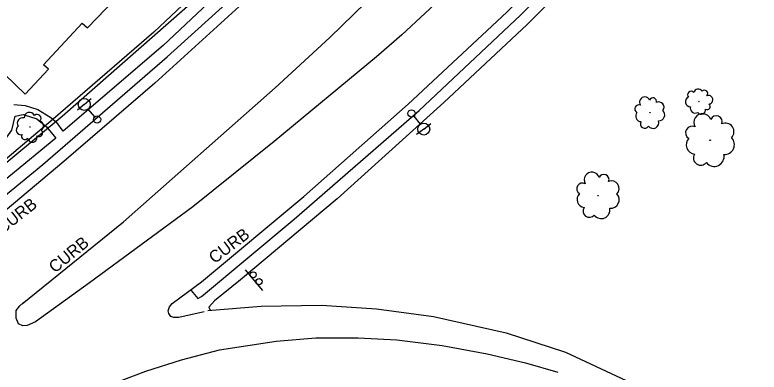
# Model space of a CAD drawing. Extents: x 1722896 to 1754269, y 648279 to 666297.
# Drawn here: x 1725529 to 1725838.8, y 657047.8 to 657196.4 of the extents above; entities that cross this region are included whole.
import ezdxf

# ---------------------------------------------------------------- set-up
doc = ezdxf.new("R2010")
doc.units = 0
for name, color, linetype in [('DESIGN - CENTERLINE - Proposed Text', 7, 'Continuous'), ('DESIGN - PUBLIC HEARING - Shapes', 7, 'Continuous'), ('DESIGN - SCRATCH - User 1', 7, 'Continuous'), ('SURVEY - CENTERLINE - Preliminary Text', 7, 'Continuous'), ('SURVEY - DTM - Breaklines', 7, 'Continuous'), ('SURVEY - VEGETATION - Features with Text', 7, 'Continuous')]:
    doc.layers.add(name, color=color, linetype=linetype)

msp = doc.modelspace()

# ---------------------------------------------------------------- linework, layer by layer
at = {"layer": 'DESIGN - CENTERLINE - Proposed Text'}
for points in [[(1725516.27, 657179.89), (1725533.34, 657163.48), (1725543.06, 657173.81), (1725540.98, 657175.6), (1725557.07, 657192.96), (1725559.27, 657191.08), (1725578.04, 657210.77)], [(1725528.54, 657159.22), (1725533.32, 657158.72), (1725538.57, 657157.14), (1725544.02, 657153.76), (1725546.52, 657151.61)], [(1725488.44, 657145.73), (1725496.96, 657140.59), (1725503.76, 657137.68), (1725510.37, 657137.1), (1725517.44, 657139.1), (1725524.03, 657143.28), (1725527.77, 657148.51), (1725529.17, 657154.37), (1725532.5, 657155.05), (1725538.16, 657153.17), (1725542.18, 657149.86)]]:
    msp.add_lwpolyline(points, dxfattribs=at)
at = {"layer": 'DESIGN - PUBLIC HEARING - Shapes'}
msp.add_line((1725632.15, 657081.75), (1725624.93, 657090.32), dxfattribs=at)
for centre in [(1725628.21, 657088.33), (1725630.62, 657085.46)]:
    msp.add_circle(centre, 1.25, dxfattribs=at)
at = {"layer": 'DESIGN - SCRATCH - User 1'}
msp.add_lwpolyline([(1725742.05, 657346.53), (1725723, 657325.09), (1725698.94, 657299.79), (1725619.93, 657220.56), (1725586.88, 657189.31), (1725544.91, 657153.09), (1725506.52, 657120.56), (1725470.29, 657167.27), (1725457.27, 657184.7), (1725456.5, 657184.15), (1725477.5, 657156.42), (1725506.66, 657119.48), (1725548.74, 657154.33), (1725605.42, 657204.22), (1725621.69, 657220.53), (1725699.14, 657298.47), (1725725.52, 657326.03), (1725742.5, 657345.81), (1725742.05, 657346.53)], dxfattribs=at)
at = {"layer": 'SURVEY - CENTERLINE - Preliminary Text'}
for points in [[(1725833.12, 657482.75), (1725835.66, 657466.48), (1725834.6, 657454.24), (1725831.44, 657439.43), (1725826.41, 657426.41), (1725818.4, 657413.79), (1725808.1, 657399.25), (1725796.47, 657385.67), (1725752.65, 657333.53), (1725710.25, 657287.4), (1725667.95, 657244.36), (1725628.49, 657205.64), (1725587.23, 657167.97), (1725549.38, 657135.48)], [(1725532.07, 657076.3), (1725574.2, 657110.35), (1725637.37, 657166.1), (1725660.07, 657187.1), (1725690.07, 657216.25), (1725721.81, 657248.12), (1725754.91, 657284.07), (1725786.69, 657319.12), (1725817.79, 657356.98), (1725845.97, 657390.57), (1725873.52, 657421.22), (1725898.55, 657448.81), (1725901.06, 657449.44), (1725903.37, 657448.44), (1725903.44, 657445.72), (1725899.57, 657420.45), (1725897.4, 657414.19), (1725893.15, 657407.78)], [(1725893.15, 657407.78), (1725869.14, 657378.83), (1725829.83, 657332.28), (1725792.43, 657289.73), (1725756.4, 657252.29), (1725723.24, 657219.05), (1725690, 657188.11), (1725679.58, 657178.98)], [(1725607.83, 657072.92), (1725597.21, 657070.49), (1725595.18, 657070.52), (1725593.88, 657071), (1725593.1, 657072.24), (1725592.86, 657073.31), (1725593.3, 657074.94), (1725594.49, 657076.33), (1725606.69, 657085.38), (1725649.32, 657120.94), (1725692.63, 657159.31), (1725733.76, 657197.57), (1725789.89, 657253.54), (1725817.33, 657283.16), (1725853.8, 657323.83), (1725890.03, 657366.92), (1725899.06, 657378.21), (1725901.84, 657379.26), (1725903.98, 657378.15), (1725905.38, 657375.6), (1725908.82, 657364.43)], [(1725602.37, 657081.85), (1725605.17, 657078.45), (1725606.68, 657079.3), (1725645.31, 657111.4), (1725697.24, 657156.73), (1725739.42, 657196.37), (1725786.94, 657243.71), (1725825.47, 657284.65), (1725865.64, 657330.37), (1725893.13, 657362.83), (1725889.47, 657365.97)], [(1725908.58, 657363.1), (1725896.71, 657359.6), (1725868.74, 657326.19), (1725830.57, 657282.8), (1725786.13, 657236.24), (1725742.28, 657192.44), (1725707.55, 657159.95), (1725663.1, 657119.88), (1725622.86, 657086.23), (1725612.13, 657077.45), (1725609.79, 657074.87), (1725610.29, 657073.63)], [(1725515.89, 657107.45), (1725512.65, 657111.3), (1725540.69, 657134.27), (1725592.43, 657179.06), (1725625.37, 657208.98), (1725663.1, 657245.93), (1725711.56, 657295.92), (1725740.56, 657328.09), (1725752.86, 657342.45)], [(1725748.06, 657344.39), (1725726.31, 657319.44), (1725682.49, 657272.69), (1725637.54, 657227.74), (1725590.72, 657183.75), (1725549.07, 657148.05), (1725546.52, 657151.61)], [(1725679.58, 657178.98), (1725636.97, 657143.75), (1725603.07, 657116.66), (1725560.02, 657084.91), (1725537.54, 657068.69), (1725534.19, 657067.27), (1725532.28, 657067.12), (1725530.55, 657067.93), (1725529.48, 657070.25), (1725529.49, 657073.42), (1725531.14, 657075.38), (1725532.6, 657076.75)], [(1725542.18, 657149.86), (1725546.12, 657145.1), (1725506.82, 657112.97), (1725488.47, 657098.71), (1725473.8, 657087.5)], [(1725549.38, 657135.48), (1725513.49, 657105.3), (1725471.68, 657072.67), (1725427.12, 657040.14), (1725377.39, 657005.82), (1725326.06, 656972.7), (1725271.47, 656940.69), (1725219.07, 656912.28), (1725204.85, 656904.26)], [(1725609.3, 657073.42), (1725631.57, 657075.3), (1725656.58, 657075.63), (1725679.57, 657074.22), (1725703.18, 657070.99), (1725733.42, 657064.15), (1725758.22, 657056.19), (1725783.48, 657044.33), (1725805.66, 657031.11), (1725828.48, 657016.26), (1725851.08, 657001.89), (1725871.32, 656991.6), (1725892.4, 656982.66), (1725912, 656975.51), (1725934.91, 656969.34), (1725955.88, 656964.74), (1725978.63, 656963.01), (1726002.9, 656962.05), (1726019.03, 656962.18), (1726040.59, 656963.08), (1726059.81, 656966.36), (1726081.67, 656971.31), (1726099.76, 656977.82), (1726113.44, 656983.76)], [(1725568.53, 657042.56), (1725583.57, 657048.2), (1725598.33, 657052.89), (1725614.15, 657057.11), (1725637.69, 657060.76), (1725654.23, 657062.08), (1725671.9, 657062.13), (1725688.02, 657061.3), (1725706.78, 657058.89), (1725725.64, 657055.5), (1725741.5, 657051.63), (1725755.05, 657047.83)]]:
    msp.add_lwpolyline(points, dxfattribs=at)
at = {"layer": 'SURVEY - DTM - Breaklines'}
for p, q in [((1725557.9, 657159.19), (1725555.04, 657156.77)), ((1725557.9, 657159.19), (1725560.77, 657161.61)), ((1725562.26, 657154.03), (1725559.52, 657157.28)), ((1725695.01, 657154.28), (1725697.62, 657150.93)), ((1725699.16, 657148.96), (1725702.11, 657151.26)), ((1725699.16, 657148.96), (1725696.2, 657146.65))]:
    msp.add_line(p, q, dxfattribs=at)
for centre, radius in [((1725557.9, 657159.19), 2.5), ((1725694.08, 657155.46), 1.5), ((1725563.23, 657152.89), 1.5), ((1725699.16, 657148.96), 2.5)]:
    msp.add_circle(centre, radius, dxfattribs=at)
at = {"layer": 'SURVEY - VEGETATION - Features with Text'}
for centre, radius in [((1725813.68, 657160.39), 0.0634), ((1725793.31, 657155.72), 0.0761), ((1725535.32, 657149.8), 0.0694), ((1725818.4, 657144.29), 0.126), ((1725771.74, 657121.24), 0.11)]:
    msp.add_circle(centre, radius, dxfattribs=at)
for centre, radius, start, end in [((1725813.41, 657163.58), 1.95, 34.4289, 161.2745), ((1725816.02, 657163.74), 1.38, 319.1418, 136.461), ((1725791.14, 657160.11), 2.18, 22.3944, 215.8141), ((1725810.16, 657160.3), 2.06, 114.3349, 270.1734), ((1725810.48, 657163.14), 1.52, 44.5878, 219.5881), ((1725817.68, 657161.13), 1.81, 276.5232, 109.9428), ((1725788.67, 657157.33), 1.66, 65.0131, 242.3323), ((1725794.57, 657160.45), 1.5, 342.3738, 161.1194), ((1725796.99, 657158.06), 2.18, 320.2576, 117.0465), ((1725817.18, 657158.3), 1.25, 236.5025, 55.2481), ((1725535.11, 657153.65), 2.25, 26.0152, 181.8536), ((1725789.71, 657154.37), 2.35, 140.3002, 267.1458), ((1725796.97, 657154.85), 2.49, 269.3104, 46.8346), ((1725812.15, 657157.66), 2.07, 163.4391, 300.9633), ((1725814.71, 657156.91), 1.82, 214.3863, 11.1752), ((1725532.28, 657151.39), 2.26, 75.1193, 212.6436), ((1725538.23, 657153.39), 1.66, 316.2681, 131.2683), ((1725815.23, 657151.75), 3.6, 19.1055, 212.5252), ((1725820.92, 657151.99), 2.48, 339.0848, 157.8304), ((1725531.55, 657148.56), 1.99, 126.0666, 282.8555), ((1725538.8, 657150.2), 2.14, 306.1091, 72.9548), ((1725791.18, 657151.12), 1.82, 150.4591, 325.4594), ((1725794.56, 657151.69), 2.47, 220.2062, 16.0447), ((1725810.89, 657147.4), 2.74, 61.7242, 239.0433), ((1725824.69, 657147.81), 3.61, 316.9687, 113.7576), ((1725533.15, 657145.9), 1.36, 148.1827, 326.9284), ((1725539.06, 657147.34), 1.51, 230.8221, 48.1412), ((1725536.26, 657145.44), 1.98, 188.2034, 21.6231), ((1725812.32, 657142.4), 3.88, 137.0112, 263.8569), ((1725824.36, 657142.52), 4.11, 266.0214, 43.5456), ((1725814.44, 657136.9), 3.01, 147.1701, 322.1704), ((1725820.08, 657137.51), 4.09, 216.9172, 12.7557), ((1725769.12, 657127.84), 3.16, 17.7354, 211.1551), ((1725774.12, 657127.94), 2.17, 337.7147, 156.4604), ((1725765.23, 657124.12), 2.4, 60.3541, 237.6732), ((1725777.33, 657124.19), 3.16, 315.5986, 112.3875), ((1725766.38, 657119.71), 3.4, 135.6411, 262.4868), ((1725776.93, 657119.56), 3.6, 264.6513, 42.1755), ((1725768.12, 657114.85), 2.64, 145.8, 320.8003), ((1725773.08, 657115.27), 3.58, 215.5471, 11.3856)]:
    msp.add_arc(centre, radius, start, end, dxfattribs=at)

# ---------------------------------------------------------------- texts
at = {"layer": 'DESIGN - SCRATCH - User 1'}
for rotation, p in [(38.195, (1725523.83, 657105.09)), (37.2091, (1725612.1, 657092.73)), (39.4558, (1725545.68, 657088.8))]:
    msp.add_text('CURB', height=5, rotation=rotation, dxfattribs=at).set_placement(p)

doc.saveas('drawing.dxf')
